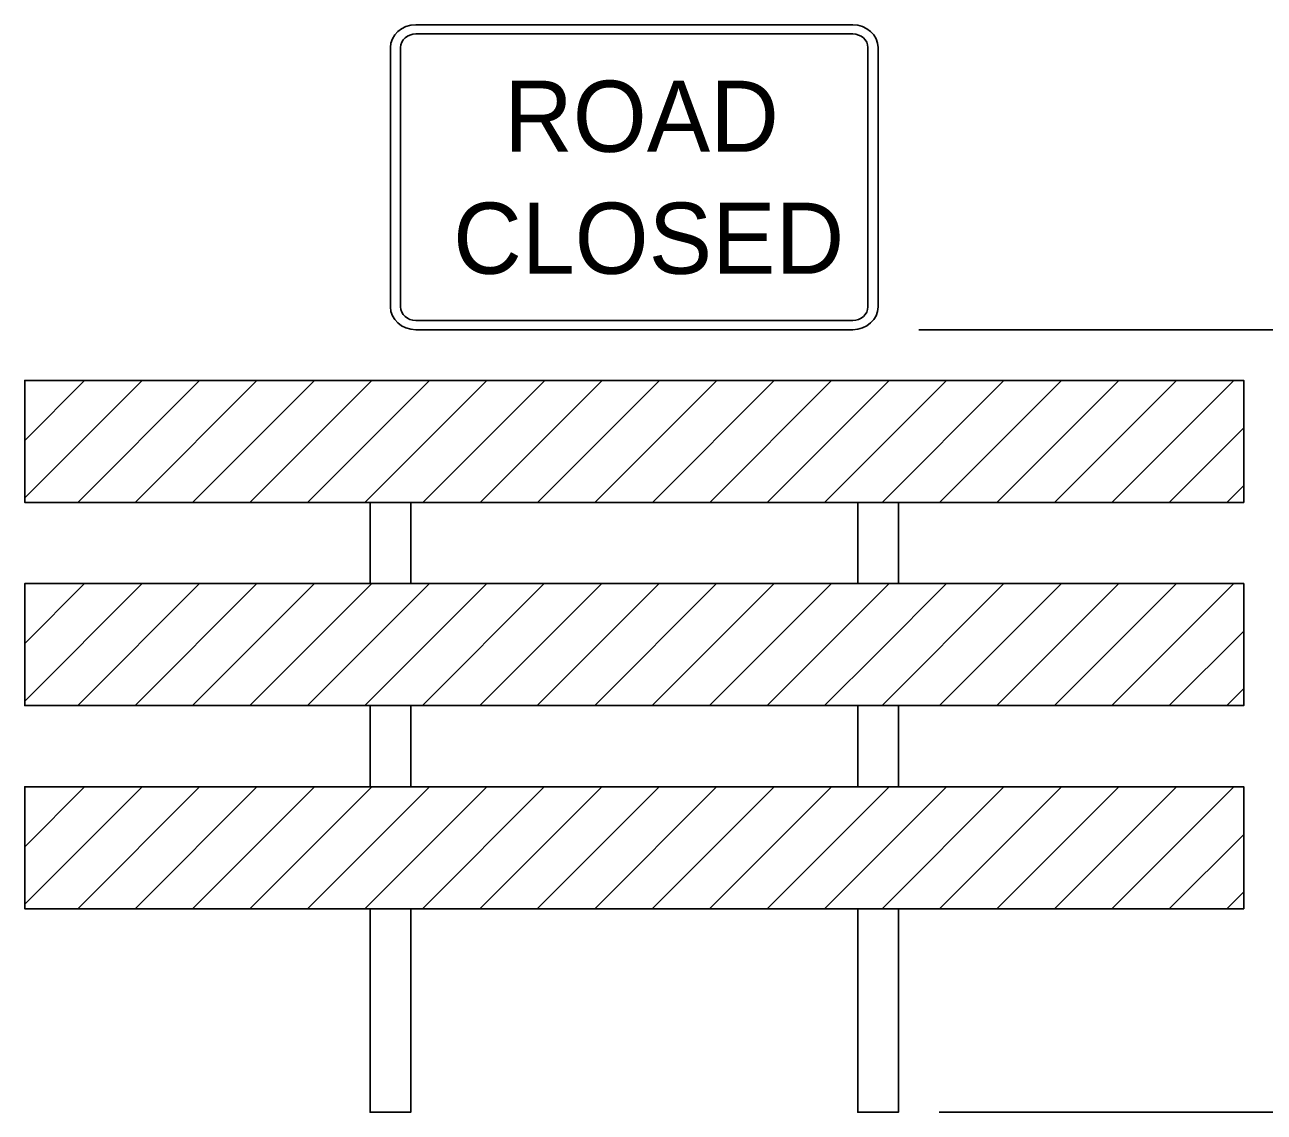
# Model space of a CAD drawing. Extents: x 49991.4 to 50021, y 49987.6 to 50011.4.
# Drawn here: x 50003.881 to 50005.101, y 49994.846 to 49995.916 of the extents above; entities that cross this region are included whole.
import ezdxf

# ---------------------------------------------------------------- set-up
doc = ezdxf.new("R2010")
doc.units = 0
doc.layers.add('Level 1', color=7, linetype='Continuous')
doc.layers.add('Level 3', color=7, linetype='Continuous')

msp = doc.modelspace()

# ---------------------------------------------------------------- linework, layer by layer
at = {"layer": 'Level 1'}
for p, q in [((50004.6961, 49995.9157), (50004.2661, 49995.9157)), ((50004.6961, 49995.9067), (50004.2661, 49995.9067)), ((50004.2411, 49995.8932), (50004.2411, 49995.6382)), ((50004.2511, 49995.8932), (50004.2511, 49995.6382)), ((50004.7111, 49995.6382), (50004.7111, 49995.8932)), ((50004.7211, 49995.6382), (50004.7211, 49995.8932)), ((50004.2661, 49995.6247), (50004.6961, 49995.6247)), ((50004.2661, 49995.6157), (50004.6961, 49995.6157)), ((50003.8811, 49995.4502), (50003.9966, 49995.5657)), ((50003.8811, 49995.5068), (50003.94, 49995.5657)), ((50003.94, 49995.5657), (50003.8811, 49995.5068)), ((50003.8811, 49995.4502), (50003.9966, 49995.5657)), ((50003.9332, 49995.4457), (50004.0532, 49995.5657)), ((50004.0532, 49995.5657), (50003.9332, 49995.4457)), ((50003.9897, 49995.4457), (50004.1097, 49995.5657)), ((50003.9897, 49995.4457), (50004.1097, 49995.5657)), ((50004.0463, 49995.4457), (50004.1663, 49995.5657)), ((50004.1663, 49995.5657), (50004.0463, 49995.4457)), ((50004.1028, 49995.4457), (50004.2228, 49995.5657)), ((50004.1028, 49995.4457), (50004.2228, 49995.5657)), ((50004.1594, 49995.4457), (50004.2794, 49995.5657)), ((50004.216, 49995.4457), (50004.336, 49995.5657)), ((50004.2411, 49995.5657), (50004.2961, 49995.5657)), ((50004.6961, 49995.5657), (50004.2661, 49995.5657)), ((50004.2729, 49995.4457), (50004.3929, 49995.5657)), ((50004.3294, 49995.4457), (50004.4494, 49995.5657)), ((50004.3859, 49995.4457), (50004.5059, 49995.5657)), ((50004.4424, 49995.4457), (50004.5624, 49995.5657)), ((50004.4989, 49995.4457), (50004.6189, 49995.5657)), ((50004.5554, 49995.4457), (50004.6754, 49995.5657)), ((50004.6119, 49995.4457), (50004.7319, 49995.5657)), ((50004.7319, 49995.5657), (50004.6619, 49995.5657)), ((50004.6684, 49995.4457), (50004.7884, 49995.5657)), ((50004.725, 49995.4457), (50004.845, 49995.5657)), ((50004.845, 49995.5657), (50004.725, 49995.4457)), ((50004.7816, 49995.4457), (50004.9016, 49995.5657)), ((50004.7816, 49995.4457), (50004.9016, 49995.5657)), ((50004.8381, 49995.4457), (50004.9581, 49995.5657)), ((50004.9581, 49995.5657), (50004.8381, 49995.4457)), ((50004.8947, 49995.4457), (50005.0147, 49995.5657)), ((50004.8947, 49995.4457), (50005.0147, 49995.5657)), ((50004.9513, 49995.4457), (50005.0713, 49995.5657)), ((50005.0713, 49995.5657), (50004.9513, 49995.4457)), ((50005.0078, 49995.4457), (50005.0811, 49995.519)), ((50005.0078, 49995.4457), (50005.0811, 49995.519)), ((50005.0644, 49995.4457), (50005.0811, 49995.4624)), ((50005.0811, 49995.4624), (50005.0644, 49995.4457)), ((50004.2611, 49995.3658), (50004.2611, 49995.4457)), ((50004.7011, 49995.3658), (50004.7011, 49995.4457)), ((50003.8811, 49995.2503), (50003.9966, 49995.3658)), ((50003.8811, 49995.3068), (50003.94, 49995.3658)), ((50003.94, 49995.3658), (50003.8811, 49995.3068)), ((50003.8811, 49995.2503), (50003.9966, 49995.3658)), ((50003.9332, 49995.2458), (50004.0532, 49995.3658)), ((50004.0532, 49995.3658), (50003.9332, 49995.2458)), ((50003.9897, 49995.2458), (50004.1097, 49995.3658)), ((50003.9897, 49995.2458), (50004.1097, 49995.3658)), ((50004.0463, 49995.2458), (50004.1663, 49995.3658)), ((50004.1663, 49995.3658), (50004.0463, 49995.2458)), ((50004.1028, 49995.2458), (50004.2228, 49995.3658)), ((50004.1028, 49995.2458), (50004.2228, 49995.3658)), ((50004.1594, 49995.2458), (50004.2794, 49995.3658)), ((50004.216, 49995.2458), (50004.336, 49995.3658)), ((50004.2725, 49995.2458), (50004.3925, 49995.3658)), ((50004.3291, 49995.2458), (50004.4491, 49995.3658)), ((50004.3856, 49995.2458), (50004.5056, 49995.3658)), ((50004.4422, 49995.2458), (50004.5622, 49995.3658)), ((50004.4988, 49995.2458), (50004.6188, 49995.3658)), ((50004.5553, 49995.2458), (50004.6753, 49995.3658)), ((50004.7211, 49995.2985), (50004.7884, 49995.3658)), ((50004.7211, 49995.355), (50004.7319, 49995.3658)), ((50004.725, 49995.2458), (50004.845, 49995.3658)), ((50004.845, 49995.3658), (50004.725, 49995.2458)), ((50004.7816, 49995.2458), (50004.9016, 49995.3658)), ((50004.7816, 49995.2458), (50004.9016, 49995.3658)), ((50004.8381, 49995.2458), (50004.9581, 49995.3658)), ((50004.9581, 49995.3658), (50004.8381, 49995.2458)), ((50004.8947, 49995.2458), (50005.0147, 49995.3658)), ((50004.8947, 49995.2458), (50005.0147, 49995.3658)), ((50004.9513, 49995.2458), (50005.0713, 49995.3658)), ((50005.0713, 49995.3658), (50004.9513, 49995.2458)), ((50004.6119, 49995.2458), (50004.7211, 49995.355)), ((50005.0078, 49995.2458), (50005.0811, 49995.319)), ((50005.0078, 49995.2458), (50005.0811, 49995.319)), ((50004.6684, 49995.2458), (50004.7211, 49995.2985)), ((50005.0644, 49995.2458), (50005.0811, 49995.2625)), ((50005.0811, 49995.2625), (50005.0644, 49995.2458)), ((50003.8811, 49995.0503), (50003.9966, 49995.1659)), ((50003.8811, 49995.1069), (50003.94, 49995.1659)), ((50003.94, 49995.1659), (50003.8811, 49995.1069)), ((50003.8811, 49995.0503), (50003.9966, 49995.1659)), ((50003.9332, 49995.0459), (50004.0532, 49995.1659)), ((50004.0532, 49995.1659), (50003.9332, 49995.0459)), ((50003.9897, 49995.0459), (50004.1097, 49995.1659)), ((50003.9897, 49995.0459), (50004.1097, 49995.1659)), ((50004.0463, 49995.0459), (50004.1663, 49995.1659)), ((50004.1663, 49995.1659), (50004.0463, 49995.0459)), ((50004.1028, 49995.0459), (50004.2228, 49995.1659)), ((50004.1028, 49995.0459), (50004.2228, 49995.1659)), ((50004.1594, 49995.0459), (50004.2794, 49995.1659)), ((50004.2794, 49995.1659), (50004.1594, 49995.0459)), ((50004.216, 49995.0459), (50004.336, 49995.1659)), ((50004.216, 49995.0459), (50004.336, 49995.1659)), ((50004.2725, 49995.0459), (50004.3925, 49995.1659)), ((50004.3925, 49995.1659), (50004.2725, 49995.0459)), ((50004.3291, 49995.0459), (50004.4491, 49995.1659)), ((50004.3291, 49995.0459), (50004.4491, 49995.1659)), ((50004.3856, 49995.0459), (50004.5056, 49995.1659)), ((50004.5056, 49995.1659), (50004.3856, 49995.0459)), ((50004.4422, 49995.0459), (50004.5622, 49995.1659)), ((50004.4422, 49995.0459), (50004.5622, 49995.1659)), ((50004.4988, 49995.0459), (50004.6188, 49995.1659)), ((50004.6188, 49995.1659), (50004.4988, 49995.0459)), ((50004.5553, 49995.0459), (50004.6753, 49995.1659)), ((50004.5553, 49995.0459), (50004.6753, 49995.1659)), ((50004.6119, 49995.0459), (50004.7319, 49995.1659)), ((50004.7319, 49995.1659), (50004.6119, 49995.0459)), ((50004.6684, 49995.0459), (50004.7884, 49995.1659)), ((50004.6684, 49995.0459), (50004.7884, 49995.1659)), ((50004.725, 49995.0459), (50004.845, 49995.1659)), ((50004.845, 49995.1659), (50004.725, 49995.0459)), ((50004.7816, 49995.0459), (50004.9016, 49995.1659)), ((50004.7816, 49995.0459), (50004.9016, 49995.1659)), ((50004.8381, 49995.0459), (50004.9581, 49995.1659)), ((50004.9581, 49995.1659), (50004.8381, 49995.0459)), ((50004.8947, 49995.0459), (50005.0147, 49995.1659)), ((50004.8947, 49995.0459), (50005.0147, 49995.1659)), ((50004.9513, 49995.0459), (50005.0713, 49995.1659)), ((50005.0713, 49995.1659), (50004.9513, 49995.0459)), ((50005.0078, 49995.0459), (50005.0811, 49995.1191)), ((50005.0078, 49995.0459), (50005.0811, 49995.1191)), ((50005.0644, 49995.0459), (50005.0811, 49995.0626)), ((50005.0811, 49995.0626), (50005.0644, 49995.0459))]:
    msp.add_line(p, q, dxfattribs=at)
for points in [[(50004.7211, 49995.4457), (50003.8811, 49995.4457), (50003.8811, 49995.5657), (50004.2411, 49995.5657)], [(50003.9966, 49995.5657), (50003.94, 49995.5657)], [(50004.1097, 49995.5657), (50004.0532, 49995.5657)], [(50004.336, 49995.5657), (50004.2961, 49995.5657), (50004.2794, 49995.5657), (50004.1594, 49995.4457), (50004.216, 49995.4457), (50004.336, 49995.5657)], [(50004.2228, 49995.5657), (50004.1663, 49995.5657)], [(50004.4494, 49995.5657), (50004.3929, 49995.5657), (50004.2729, 49995.4457), (50004.3294, 49995.4457), (50004.4494, 49995.5657)], [(50004.5624, 49995.5657), (50004.5059, 49995.5657), (50004.3859, 49995.4457), (50004.4424, 49995.4457), (50004.5624, 49995.5657)], [(50004.6754, 49995.5657), (50004.6619, 49995.5657), (50004.6189, 49995.5657), (50004.4989, 49995.4457), (50004.5554, 49995.4457), (50004.6754, 49995.5657)], [(50004.6119, 49995.4457), (50004.6684, 49995.4457), (50004.7884, 49995.5657), (50004.7319, 49995.5657), (50004.6119, 49995.4457)], [(50004.7211, 49995.5657), (50005.0811, 49995.5657), (50005.0811, 49995.4457), (50004.7211, 49995.4457)], [(50004.9016, 49995.5657), (50004.845, 49995.5657)], [(50005.0147, 49995.5657), (50004.9581, 49995.5657)], [(50005.0811, 49995.519), (50005.0811, 49995.5657), (50005.0713, 49995.5657)], [(50003.8811, 49995.5068), (50003.8811, 49995.4502)], [(50005.0644, 49995.4457), (50005.0811, 49995.4457), (50005.0811, 49995.4624)], [(50003.9332, 49995.4457), (50003.9897, 49995.4457)], [(50004.0463, 49995.4457), (50004.1028, 49995.4457)], [(50004.2211, 49995.3657), (50004.2211, 49995.4457)], [(50004.725, 49995.4457), (50004.7816, 49995.4457)], [(50004.7411, 49995.4457), (50004.7411, 49995.3658)], [(50004.8381, 49995.4457), (50004.8947, 49995.4457)], [(50004.9513, 49995.4457), (50005.0078, 49995.4457)], [(50004.7211, 49995.3658), (50005.0811, 49995.3658), (50005.0811, 49995.2458), (50003.8811, 49995.2458), (50003.8811, 49995.3658), (50004.7211, 49995.3658)], [(50003.9966, 49995.3658), (50003.94, 49995.3658)], [(50004.1097, 49995.3658), (50004.0532, 49995.3658)], [(50004.336, 49995.3658), (50004.2794, 49995.3658), (50004.1594, 49995.2458), (50004.216, 49995.2458), (50004.336, 49995.3658)], [(50004.2228, 49995.3658), (50004.1663, 49995.3658)], [(50004.4491, 49995.3658), (50004.3925, 49995.3658), (50004.2725, 49995.2458), (50004.3291, 49995.2458), (50004.4491, 49995.3658)], [(50004.5622, 49995.3658), (50004.5056, 49995.3658), (50004.3856, 49995.2458), (50004.4422, 49995.2458), (50004.5622, 49995.3658)], [(50004.6753, 49995.3658), (50004.6188, 49995.3658), (50004.4988, 49995.2458), (50004.5553, 49995.2458), (50004.6753, 49995.3658)], [(50004.6119, 49995.2458), (50004.6684, 49995.2458), (50004.7211, 49995.2985), (50004.7884, 49995.3658), (50004.7411, 49995.3658), (50004.7319, 49995.3658), (50004.7211, 49995.355), (50004.6119, 49995.2458)], [(50004.9016, 49995.3658), (50004.845, 49995.3658)], [(50005.0147, 49995.3658), (50004.9581, 49995.3658)], [(50005.0811, 49995.319), (50005.0811, 49995.3658), (50005.0713, 49995.3658)], [(50003.8811, 49995.3068), (50003.8811, 49995.2503)], [(50005.0644, 49995.2458), (50005.0811, 49995.2458), (50005.0811, 49995.2625)], [(50003.9332, 49995.2458), (50003.9897, 49995.2458)], [(50004.0463, 49995.2458), (50004.1028, 49995.2458)], [(50004.2211, 49995.1659), (50004.2211, 49995.2458)], [(50004.2611, 49995.2458), (50004.2611, 49995.1659)], [(50004.7011, 49995.1659), (50004.7011, 49995.2458)], [(50004.725, 49995.2458), (50004.7816, 49995.2458)], [(50004.7411, 49995.2458), (50004.7411, 49995.1659)], [(50004.8381, 49995.2458), (50004.8947, 49995.2458)], [(50004.9513, 49995.2458), (50005.0078, 49995.2458)], [(50004.7884, 49995.1659), (50005.0811, 49995.1659), (50005.0811, 49995.0459), (50003.8811, 49995.0459), (50003.8811, 49995.1659), (50004.1663, 49995.1659)], [(50003.9966, 49995.1659), (50003.94, 49995.1659)], [(50004.1097, 49995.1659), (50004.0532, 49995.1659)], [(50004.2228, 49995.1659), (50004.1663, 49995.1659)], [(50004.2228, 49995.1659), (50004.7319, 49995.1659)], [(50004.336, 49995.1659), (50004.2794, 49995.1659)], [(50004.4491, 49995.1659), (50004.3925, 49995.1659)], [(50004.5622, 49995.1659), (50004.5056, 49995.1659)], [(50004.6753, 49995.1659), (50004.6188, 49995.1659)], [(50004.7884, 49995.1659), (50004.7319, 49995.1659)], [(50004.9016, 49995.1659), (50004.845, 49995.1659)], [(50005.0147, 49995.1659), (50004.9581, 49995.1659)], [(50005.0811, 49995.1191), (50005.0811, 49995.1659), (50005.0713, 49995.1659)], [(50003.8811, 49995.1069), (50003.8811, 49995.0503)], [(50005.0644, 49995.0459), (50005.0811, 49995.0459), (50005.0811, 49995.0626)], [(50003.9332, 49995.0459), (50003.9897, 49995.0459)], [(50004.0463, 49995.0459), (50004.1028, 49995.0459)], [(50004.1594, 49995.0459), (50004.216, 49995.0459)], [(50004.2611, 49995.0457), (50004.2611, 49994.8457), (50004.2211, 49994.8457), (50004.2211, 49995.0457)], [(50004.2725, 49995.0459), (50004.3291, 49995.0459)], [(50004.3856, 49995.0459), (50004.4422, 49995.0459)], [(50004.4988, 49995.0459), (50004.5553, 49995.0459)], [(50004.6119, 49995.0459), (50004.6684, 49995.0459)], [(50004.7411, 49995.0457), (50004.7411, 49994.8457), (50004.7011, 49994.8457), (50004.7011, 49995.0457)], [(50004.725, 49995.0459), (50004.7816, 49995.0459)], [(50004.8381, 49995.0459), (50004.8947, 49995.0459)], [(50004.9513, 49995.0459), (50005.0078, 49995.0459)]]:
    msp.add_lwpolyline(points, dxfattribs=at)
for centre, major_axis, start_param, end_param in [((50004.2661, 49995.8932), (-0.025, 0), 4.712389, 6.283185), ((50004.6961, 49995.8932), (0.025, 0), 0, 1.570796), ((50004.2661, 49995.8932), (-0.015, 0), 4.712389, 6.283185), ((50004.6961, 49995.8932), (0.015, 0), 0, 1.570796), ((50004.2661, 49995.6382), (-0.025, 0), 0, 1.570796), ((50004.2661, 49995.6382), (-0.015, 0), 0, 1.570796), ((50004.6961, 49995.6382), (0.025, 0), 4.712389, 6.283185), ((50004.6961, 49995.6382), (0.015, 0), 4.712389, 6.283185)]:
    msp.add_ellipse(centre, major_axis=major_axis, ratio=0.9, start_param=start_param, end_param=end_param, dxfattribs=at)
at = {"layer": 'Level 3'}
for p, q in [((50004.7611, 49995.6157), (50005.9211, 49995.6157)), ((50004.7811, 49994.8457), (50005.9211, 49994.8457))]:
    msp.add_line(p, q, dxfattribs=at)

# ---------------------------------------------------------------- texts
at = {"layer": 'Level 1'}
for s, p in [('ROAD', (50004.353, 49995.7907)), ('CLOSED', (50004.3028, 49995.6707))]:
    msp.add_text(s, height=0.07, dxfattribs=at).set_placement(p)

doc.saveas('drawing.dxf')
